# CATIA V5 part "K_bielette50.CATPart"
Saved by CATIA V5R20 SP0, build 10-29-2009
Part number: biellette 50
Publications: "demi largeur balancier", "epaisseur pieces", "Plan.-30", "liaison 57/50", "liaison 51/50"
Bounding box of the stored display mesh (mm): x -60 to -30, y -680 to -525, z 745 to 815
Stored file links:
  G:\Khaled_CFAO_2011\SIL\SIL_GR2\mdardier\Khaled\CAD_ThinkMOTION\K_bielette50.CATPart
  G:\Khaled_CFAO_2011\SIL\SIL_GR2\mdardier\Khaled\CAD_ThinkMOTION\K_ass_tandem.CATProduct
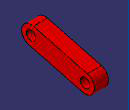
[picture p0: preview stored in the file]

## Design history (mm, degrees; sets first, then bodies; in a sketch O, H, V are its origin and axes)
External parameters (linked from other documents)
  `External.demi largeur balancier` = 50 mm
  `External.epaisseur pieces` = 30 mm
Set1
  Plane1 "Plan.-30": linked copy from another document
  Point1 "liaison 57/50": linked copy from another document
  Point2 "liaison 51/50": linked copy from another document
Body1 (main body)
  Sketch1 on Plane1, origin (-30, 0, 0), H (0, 1, 0), V (0, 0, 1)
    construction line L1 (-660, 795) -> (-545, 765)
    point P1 (-660, 795)
    point P2 (-545, 765)
    line L2 (-654.9516, 814.3523) -> (-539.9516, 784.3523)
    line L3 (-550.0484, 745.6477) -> (-665.0484, 775.6477)
    arc A1 centre (-545, 765) radius 20 from (-539.9516, 784.3523) to (-550.0484, 745.6477) cw
    arc A2 centre (-660, 795) radius 20 from (-665.0484, 775.6477) to (-654.9516, 814.3523) cw
    reference projected point E1 (-660, 795) from Point1
    reference projected point E2 (-545, 765) from Point2
    circle A3 centre (-660, 795) radius 10
    point P7 (-660, 795)
    reference projected point E3 (-660, 795) from Point1
    circle A4 centre (-545, 765) radius 10
    point P8 (-545, 765)
    reference projected point E4 (-545, 765) from Point2
    distance L1 L2 = 20 {= `External.demi largeur balancier` *2/5}
    radius A4 = 10 {= `External.demi largeur balancier` /5}
    radius A3 = 10 {= `External.demi largeur balancier` /5}
    tangency: A1 L2, A2 L2, A1 L3, A2 L3
    coincidence: P1 E1, P2 E2, P7 E3, P8 E4
  Pad1: profile Sketch1, direction (-1, 0, 0), length 30 {= `External.epaisseur pieces`}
